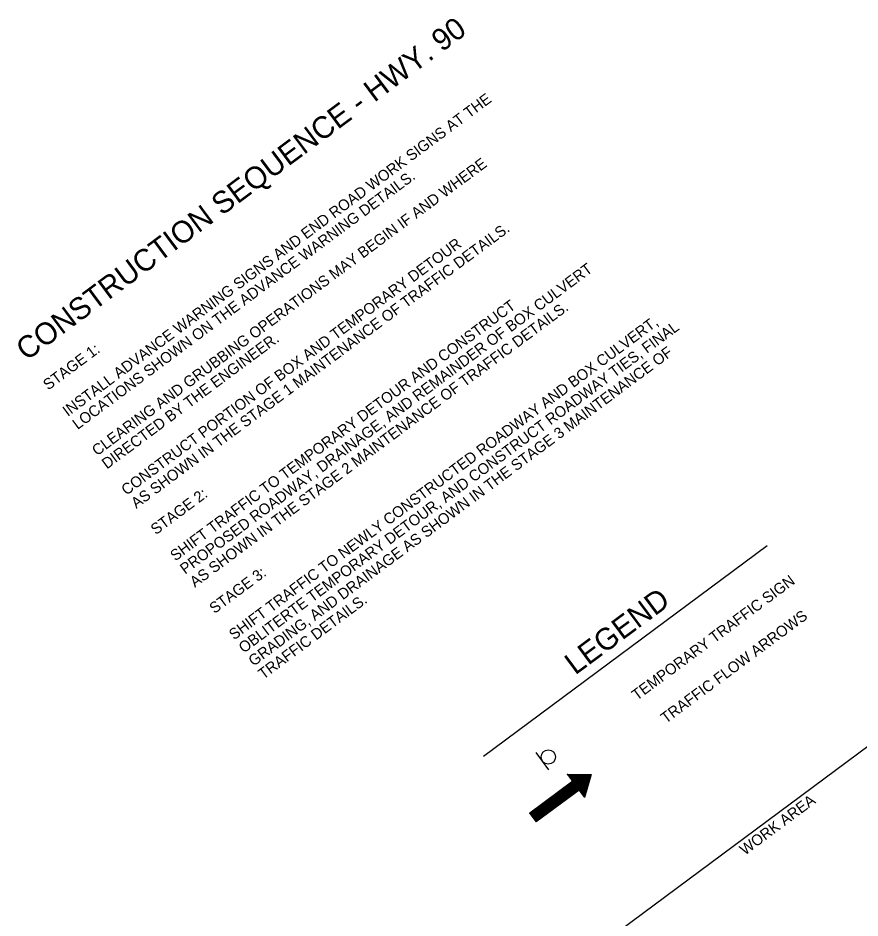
# Model space of a CAD drawing. Extents: x 998982 to 1000630, y 1875366 to 1876934.
# Drawn here: x 999331.9 to 999794.4, y 1876029.3 to 1876523.6 of the extents above; entities that cross this region are included whole.
import ezdxf

# ---------------------------------------------------------------- set-up
doc = ezdxf.new("R2010")
doc.units = 0
for name, color, linetype in [('R_Border Prem', 7, 'Continuous'), ('R_Draft', 7, 'Continuous'), ('STAMP', 7, 'Continuous')]:
    doc.layers.add(name, color=color, linetype=linetype)

msp = doc.modelspace()

# ---------------------------------------------------------------- linework, layer by layer
at = {"layer": 'R_Border Prem'}
for p, q in [((999587.66, 1876118.2), (999743.35, 1876233.81)), ((999633.68, 1876108.29), (999633.69, 1876108.36)), ((999633.76, 1876108.18), (999633.79, 1876108.36)), ((999633.84, 1876108.07), (999633.89, 1876108.36)), ((999633.93, 1876107.95), (999633.99, 1876108.36)), ((999634.01, 1876107.84), (999634.09, 1876108.36)), ((999634.1, 1876107.72), (999634.19, 1876108.35)), ((999634.18, 1876107.61), (999634.29, 1876108.35)), ((999634.27, 1876107.5), (999634.39, 1876108.35)), ((999634.35, 1876107.38), (999634.49, 1876108.35)), ((999634.43, 1876107.27), (999634.59, 1876108.35)), ((999634.52, 1876107.16), (999634.69, 1876108.35)), ((999634.6, 1876107.04), (999634.8, 1876108.34)), ((999634.69, 1876106.93), (999634.9, 1876108.34)), ((999634.77, 1876106.82), (999635, 1876108.34)), ((999634.86, 1876106.7), (999635.1, 1876108.34)), ((999634.94, 1876106.59), (999635.2, 1876108.34)), ((999635.02, 1876106.48), (999635.3, 1876108.34)), ((999635.11, 1876106.36), (999635.4, 1876108.33)), ((999635.19, 1876106.25), (999635.5, 1876108.33)), ((999635.28, 1876106.14), (999635.6, 1876108.33)), ((999635.36, 1876106.02), (999635.7, 1876108.33)), ((999635.4, 1876096.02), (999637.22, 1876108.3)), ((999635.45, 1876105.91), (999635.8, 1876108.33)), ((999635.51, 1876096.1), (999637.32, 1876108.3)), ((999635.53, 1876105.79), (999635.9, 1876108.32)), ((999635.62, 1876105.68), (999636.01, 1876108.32)), ((999635.63, 1876096.19), (999637.42, 1876108.3)), ((999635.7, 1876105.57), (999636.11, 1876108.32)), ((999635.74, 1876096.27), (999637.52, 1876108.3)), ((999635.78, 1876105.45), (999636.21, 1876108.32)), ((999635.85, 1876096.36), (999637.62, 1876108.29)), ((999635.87, 1876105.34), (999636.31, 1876108.32)), ((999635.95, 1876105.23), (999636.41, 1876108.32)), ((999635.97, 1876096.44), (999637.72, 1876108.29)), ((999636.04, 1876105.11), (999636.51, 1876108.31)), ((999636.08, 1876096.53), (999637.82, 1876108.29)), ((999636.12, 1876105), (999636.61, 1876108.31)), ((999636.2, 1876096.61), (999637.92, 1876108.29)), ((999636.21, 1876104.89), (999636.71, 1876108.31)), ((999636.29, 1876104.77), (999636.81, 1876108.31)), ((999636.31, 1876096.69), (999638.02, 1876108.29)), ((999636.37, 1876104.66), (999636.91, 1876108.31)), ((999636.42, 1876096.78), (999638.12, 1876108.28)), ((999636.46, 1876104.55), (999637.01, 1876108.3)), ((999636.54, 1876104.43), (999637.11, 1876108.3)), ((999636.54, 1876096.86), (999638.22, 1876108.28)), ((999636.65, 1876096.95), (999638.32, 1876108.28)), ((999636.76, 1876097.03), (999638.43, 1876108.28)), ((999636.88, 1876097.12), (999638.53, 1876108.28)), ((999636.99, 1876097.2), (999638.63, 1876108.28)), ((999637.1, 1876097.28), (999638.73, 1876108.27)), ((999637.22, 1876097.37), (999638.83, 1876108.27)), ((999637.33, 1876097.45), (999638.93, 1876108.27)), ((999637.44, 1876097.54), (999639.03, 1876108.27)), ((999637.56, 1876097.62), (999639.13, 1876108.27)), ((999637.67, 1876097.71), (999639.23, 1876108.26)), ((999637.79, 1876097.79), (999639.33, 1876108.26)), ((999637.9, 1876097.87), (999639.43, 1876108.26)), ((999638.01, 1876097.96), (999639.53, 1876108.26)), ((999638.13, 1876098.04), (999639.63, 1876108.26)), ((999638.24, 1876098.13), (999639.74, 1876108.26)), ((999638.35, 1876098.21), (999639.84, 1876108.25)), ((999638.47, 1876098.3), (999639.94, 1876108.25)), ((999638.58, 1876098.38), (999640.04, 1876108.25)), ((999638.69, 1876098.46), (999640.14, 1876108.25)), ((999638.81, 1876098.55), (999640.24, 1876108.25)), ((999638.92, 1876098.63), (999640.34, 1876108.25)), ((999639.03, 1876098.72), (999640.44, 1876108.24)), ((999639.15, 1876098.8), (999640.54, 1876108.24)), ((999639.26, 1876098.89), (999640.64, 1876108.24)), ((999639.37, 1876098.97), (999640.74, 1876108.24)), ((999639.49, 1876099.05), (999640.84, 1876108.24)), ((999639.6, 1876099.14), (999640.95, 1876108.23)), ((999639.72, 1876099.22), (999641.05, 1876108.23)), ((999639.83, 1876099.31), (999641.15, 1876108.23)), ((999639.94, 1876099.39), (999641.25, 1876108.23)), ((999640.06, 1876099.48), (999641.35, 1876108.23)), ((999640.17, 1876099.55), (999641.45, 1876108.23)), ((999640.25, 1876099.44), (999641.55, 1876108.22)), ((999640.34, 1876099.32), (999641.65, 1876108.22)), ((999640.42, 1876099.21), (999641.75, 1876108.22)), ((999640.51, 1876099.1), (999641.85, 1876108.22)), ((999640.59, 1876098.98), (999641.95, 1876108.22)), ((999640.67, 1876098.87), (999642.05, 1876108.21)), ((999640.76, 1876098.75), (999642.16, 1876108.21)), ((999640.84, 1876098.64), (999642.26, 1876108.21)), ((999640.93, 1876098.53), (999642.36, 1876108.21)), ((999641.01, 1876098.41), (999642.46, 1876108.21)), ((999641.1, 1876098.3), (999642.56, 1876108.21)), ((999641.18, 1876098.19), (999642.66, 1876108.2)), ((999641.26, 1876098.07), (999642.76, 1876108.2)), ((999641.35, 1876097.96), (999642.86, 1876108.2)), ((999641.43, 1876097.85), (999642.96, 1876108.2)), ((999641.52, 1876097.73), (999643.06, 1876108.2)), ((999641.6, 1876097.62), (999643.16, 1876108.19)), ((999641.69, 1876097.51), (999643.26, 1876108.19)), ((999641.77, 1876097.39), (999643.37, 1876108.19)), ((999641.85, 1876097.28), (999643.47, 1876108.19)), ((999641.94, 1876097.17), (999643.57, 1876108.19)), ((999642.02, 1876097.05), (999643.67, 1876108.19)), ((999642.11, 1876096.94), (999643.77, 1876108.18)), ((999642.19, 1876096.82), (999643.87, 1876108.18)), ((999642.28, 1876096.71), (999643.97, 1876108.18)), ((999642.36, 1876096.6), (999644.07, 1876108.18)), ((999642.44, 1876096.48), (999644.17, 1876108.18)), ((999642.53, 1876096.37), (999644.27, 1876108.17)), ((999642.61, 1876096.26), (999644.37, 1876108.17)), ((999642.7, 1876096.14), (999644.47, 1876108.17)), ((999642.78, 1876096.03), (999644.58, 1876108.17)), ((999642.87, 1876095.92), (999644.68, 1876108.17)), ((999642.95, 1876095.8), (999644.78, 1876108.17)), ((999643.03, 1876095.69), (999644.88, 1876108.16)), ((999643.12, 1876095.58), (999644.98, 1876108.16)), ((999643.3, 1876096.14), (999645.08, 1876108.16)), ((999643.52, 1876096.89), (999645.18, 1876108.16)), ((999643.73, 1876097.64), (999645.28, 1876108.16)), ((999643.94, 1876098.39), (999645.38, 1876108.16)), ((999644.15, 1876099.14), (999645.48, 1876108.15)), ((999644.36, 1876099.89), (999645.58, 1876108.15)), ((999644.57, 1876100.64), (999645.68, 1876108.15)), ((999644.79, 1876101.39), (999645.78, 1876108.15)), ((999645, 1876102.14), (999645.89, 1876108.15)), ((999645.21, 1876102.88), (999645.99, 1876108.14)), ((999645.42, 1876103.63), (999646.09, 1876108.14)), ((999645.63, 1876104.38), (999646.19, 1876108.14)), ((999645.84, 1876105.13), (999646.29, 1876108.14)), ((999646.06, 1876105.88), (999646.39, 1876108.14)), ((999646.27, 1876106.63), (999646.49, 1876108.14)), ((999646.48, 1876107.38), (999646.59, 1876108.13)), ((999646.69, 1876108.13), (999646.69, 1876108.13)), ((999633.02, 1876094.25), (999634.25, 1876102.62)), ((999633.13, 1876094.33), (999634.37, 1876102.71)), ((999633.24, 1876094.42), (999634.48, 1876102.79)), ((999633.36, 1876094.5), (999634.59, 1876102.87)), ((999633.47, 1876094.59), (999634.71, 1876102.96)), ((999633.58, 1876094.67), (999634.82, 1876103.04)), ((999633.7, 1876094.76), (999634.93, 1876103.13)), ((999633.81, 1876094.84), (999635.05, 1876103.21)), ((999633.92, 1876094.92), (999635.16, 1876103.3)), ((999634.04, 1876095.01), (999635.28, 1876103.38)), ((999634.15, 1876095.09), (999635.39, 1876103.46)), ((999634.27, 1876095.18), (999635.5, 1876103.55)), ((999634.38, 1876095.26), (999635.62, 1876103.63)), ((999634.49, 1876095.35), (999635.73, 1876103.72)), ((999634.61, 1876095.43), (999635.84, 1876103.8)), ((999634.72, 1876095.51), (999635.96, 1876103.89)), ((999634.83, 1876095.6), (999636.07, 1876103.97)), ((999634.95, 1876095.68), (999636.18, 1876104.06)), ((999635.06, 1876095.77), (999636.3, 1876104.14)), ((999635.17, 1876095.85), (999636.41, 1876104.22)), ((999635.29, 1876095.94), (999636.52, 1876104.31)), ((999626.43, 1876089.36), (999627.67, 1876097.73)), ((999626.54, 1876089.44), (999627.78, 1876097.82)), ((999626.66, 1876089.53), (999627.9, 1876097.9)), ((999626.77, 1876089.61), (999628.01, 1876097.98)), ((999626.89, 1876089.7), (999628.12, 1876098.07)), ((999627, 1876089.78), (999628.24, 1876098.15)), ((999627.11, 1876089.87), (999628.35, 1876098.24)), ((999627.23, 1876089.95), (999628.46, 1876098.32)), ((999627.34, 1876090.03), (999628.58, 1876098.41)), ((999627.45, 1876090.12), (999628.69, 1876098.49)), ((999627.57, 1876090.2), (999628.8, 1876098.58)), ((999627.68, 1876090.29), (999628.92, 1876098.66)), ((999627.79, 1876090.37), (999629.03, 1876098.74)), ((999627.91, 1876090.46), (999629.14, 1876098.83)), ((999628.02, 1876090.54), (999629.26, 1876098.91)), ((999628.13, 1876090.62), (999629.37, 1876099)), ((999628.25, 1876090.71), (999629.48, 1876099.08)), ((999628.36, 1876090.79), (999629.6, 1876099.17)), ((999628.47, 1876090.88), (999629.71, 1876099.25)), ((999628.59, 1876090.96), (999629.83, 1876099.33)), ((999628.7, 1876091.05), (999629.94, 1876099.42)), ((999628.82, 1876091.13), (999630.05, 1876099.5)), ((999628.93, 1876091.21), (999630.17, 1876099.59)), ((999629.04, 1876091.3), (999630.28, 1876099.67)), ((999629.16, 1876091.38), (999630.39, 1876099.76)), ((999629.27, 1876091.47), (999630.51, 1876099.84)), ((999629.38, 1876091.55), (999630.62, 1876099.92)), ((999629.5, 1876091.64), (999630.73, 1876100.01)), ((999629.61, 1876091.72), (999630.85, 1876100.09)), ((999629.72, 1876091.8), (999630.96, 1876100.18)), ((999629.84, 1876091.89), (999631.07, 1876100.26)), ((999629.95, 1876091.97), (999631.19, 1876100.35)), ((999630.06, 1876092.06), (999631.3, 1876100.43)), ((999630.18, 1876092.14), (999631.41, 1876100.51)), ((999630.29, 1876092.23), (999631.53, 1876100.6)), ((999630.4, 1876092.31), (999631.64, 1876100.68)), ((999630.52, 1876092.39), (999631.76, 1876100.77)), ((999630.63, 1876092.48), (999631.87, 1876100.85)), ((999630.75, 1876092.56), (999631.98, 1876100.94)), ((999630.86, 1876092.65), (999632.1, 1876101.02)), ((999630.97, 1876092.73), (999632.21, 1876101.1)), ((999631.09, 1876092.82), (999632.32, 1876101.19)), ((999631.2, 1876092.9), (999632.44, 1876101.27)), ((999631.31, 1876092.98), (999632.55, 1876101.36)), ((999631.43, 1876093.07), (999632.66, 1876101.44)), ((999631.54, 1876093.15), (999632.78, 1876101.53)), ((999631.65, 1876093.24), (999632.89, 1876101.61)), ((999631.77, 1876093.32), (999633, 1876101.69)), ((999631.88, 1876093.41), (999633.12, 1876101.78)), ((999631.99, 1876093.49), (999633.23, 1876101.86)), ((999632.11, 1876093.57), (999633.35, 1876101.95)), ((999632.22, 1876093.66), (999633.46, 1876102.03)), ((999632.34, 1876093.74), (999633.57, 1876102.12)), ((999632.45, 1876093.83), (999633.69, 1876102.2)), ((999632.56, 1876093.91), (999633.8, 1876102.28)), ((999632.68, 1876094), (999633.91, 1876102.37)), ((999632.79, 1876094.08), (999634.03, 1876102.45)), ((999632.9, 1876094.16), (999634.14, 1876102.54)), ((999619.73, 1876084.38), (999620.97, 1876092.76)), ((999619.85, 1876084.47), (999621.08, 1876092.84)), ((999619.96, 1876084.55), (999621.2, 1876092.93)), ((999620.07, 1876084.64), (999621.31, 1876093.01)), ((999620.19, 1876084.72), (999621.42, 1876093.09)), ((999620.3, 1876084.81), (999621.54, 1876093.18)), ((999620.41, 1876084.89), (999621.65, 1876093.26)), ((999620.53, 1876084.98), (999621.76, 1876093.35)), ((999620.64, 1876085.06), (999621.88, 1876093.43)), ((999620.75, 1876085.14), (999621.99, 1876093.52)), ((999620.87, 1876085.23), (999622.1, 1876093.6)), ((999620.98, 1876085.31), (999622.22, 1876093.69)), ((999621.09, 1876085.4), (999622.33, 1876093.77)), ((999621.21, 1876085.48), (999622.44, 1876093.85)), ((999621.32, 1876085.57), (999622.56, 1876093.94)), ((999621.44, 1876085.65), (999622.67, 1876094.02)), ((999621.55, 1876085.73), (999622.79, 1876094.11)), ((999621.66, 1876085.82), (999622.9, 1876094.19)), ((999621.78, 1876085.9), (999623.01, 1876094.28)), ((999621.89, 1876085.99), (999623.13, 1876094.36)), ((999622, 1876086.07), (999623.24, 1876094.44)), ((999622.12, 1876086.16), (999623.35, 1876094.53)), ((999622.23, 1876086.24), (999623.47, 1876094.61)), ((999622.34, 1876086.32), (999623.58, 1876094.7)), ((999622.46, 1876086.41), (999623.69, 1876094.78)), ((999622.57, 1876086.49), (999623.81, 1876094.87)), ((999622.68, 1876086.58), (999623.92, 1876094.95)), ((999622.8, 1876086.66), (999624.03, 1876095.03)), ((999622.91, 1876086.75), (999624.15, 1876095.12)), ((999623.02, 1876086.83), (999624.26, 1876095.2)), ((999623.14, 1876086.91), (999624.38, 1876095.29)), ((999623.25, 1876087), (999624.49, 1876095.37)), ((999623.37, 1876087.08), (999624.6, 1876095.46)), ((999623.48, 1876087.17), (999624.72, 1876095.54)), ((999623.59, 1876087.25), (999624.83, 1876095.62)), ((999623.71, 1876087.34), (999624.94, 1876095.71)), ((999623.82, 1876087.42), (999625.06, 1876095.79)), ((999623.93, 1876087.5), (999625.17, 1876095.88)), ((999624.05, 1876087.59), (999625.28, 1876095.96)), ((999624.16, 1876087.67), (999625.4, 1876096.05)), ((999624.27, 1876087.76), (999625.51, 1876096.13)), ((999624.39, 1876087.84), (999625.62, 1876096.21)), ((999624.5, 1876087.93), (999625.74, 1876096.3)), ((999624.61, 1876088.01), (999625.85, 1876096.38)), ((999624.73, 1876088.09), (999625.96, 1876096.47)), ((999624.84, 1876088.18), (999626.08, 1876096.55)), ((999624.95, 1876088.26), (999626.19, 1876096.64)), ((999625.07, 1876088.35), (999626.31, 1876096.72)), ((999625.18, 1876088.43), (999626.42, 1876096.8)), ((999625.3, 1876088.52), (999626.53, 1876096.89)), ((999625.41, 1876088.6), (999626.65, 1876096.97)), ((999625.52, 1876088.68), (999626.76, 1876097.06)), ((999625.64, 1876088.77), (999626.87, 1876097.14)), ((999625.75, 1876088.85), (999626.99, 1876097.23)), ((999625.86, 1876088.94), (999627.1, 1876097.31)), ((999625.98, 1876089.02), (999627.21, 1876097.39)), ((999626.09, 1876089.11), (999627.33, 1876097.48)), ((999626.2, 1876089.19), (999627.44, 1876097.56)), ((999626.32, 1876089.27), (999627.55, 1876097.65)), ((999613.95, 1876085.63), (999614.27, 1876087.78)), ((999614.04, 1876085.52), (999614.38, 1876087.87)), ((999614.12, 1876085.4), (999614.5, 1876087.95)), ((999614.2, 1876085.29), (999614.61, 1876088.04)), ((999614.29, 1876085.17), (999614.72, 1876088.12)), ((999614.37, 1876085.06), (999614.84, 1876088.2)), ((999614.46, 1876084.95), (999614.95, 1876088.29)), ((999614.54, 1876084.83), (999615.06, 1876088.37)), ((999614.63, 1876084.72), (999615.18, 1876088.46)), ((999614.71, 1876084.61), (999615.29, 1876088.54)), ((999614.79, 1876084.49), (999615.41, 1876088.63)), ((999614.88, 1876084.38), (999615.52, 1876088.71)), ((999614.96, 1876084.27), (999615.63, 1876088.8)), ((999615.05, 1876084.15), (999615.75, 1876088.88)), ((999615.13, 1876084.04), (999615.86, 1876088.96)), ((999615.22, 1876083.93), (999615.97, 1876089.05)), ((999615.3, 1876083.81), (999616.09, 1876089.13)), ((999615.38, 1876083.7), (999616.2, 1876089.22)), ((999615.47, 1876083.58), (999616.31, 1876089.3)), ((999615.55, 1876083.47), (999616.43, 1876089.39)), ((999615.64, 1876083.36), (999616.54, 1876089.47)), ((999615.72, 1876083.24), (999616.65, 1876089.55)), ((999615.81, 1876083.13), (999616.77, 1876089.64)), ((999615.89, 1876083.02), (999616.88, 1876089.72)), ((999615.97, 1876082.9), (999616.99, 1876089.81)), ((999616.06, 1876082.79), (999617.11, 1876089.89)), ((999616.14, 1876082.68), (999617.22, 1876089.98)), ((999616.23, 1876082.56), (999617.34, 1876090.06)), ((999616.31, 1876082.45), (999617.45, 1876090.14)), ((999616.4, 1876082.34), (999617.56, 1876090.23)), ((999616.48, 1876082.22), (999617.68, 1876090.31)), ((999616.57, 1876082.11), (999617.79, 1876090.4)), ((999616.67, 1876082.11), (999617.9, 1876090.48)), ((999616.78, 1876082.19), (999618.02, 1876090.57)), ((999616.89, 1876082.28), (999618.13, 1876090.65)), ((999617.01, 1876082.36), (999618.24, 1876090.73)), ((999617.12, 1876082.45), (999618.36, 1876090.82)), ((999617.23, 1876082.53), (999618.47, 1876090.9)), ((999617.35, 1876082.61), (999618.58, 1876090.99)), ((999617.46, 1876082.7), (999618.7, 1876091.07)), ((999617.57, 1876082.78), (999618.81, 1876091.16)), ((999617.69, 1876082.87), (999618.93, 1876091.24)), ((999617.8, 1876082.95), (999619.04, 1876091.32)), ((999617.92, 1876083.04), (999619.15, 1876091.41)), ((999618.03, 1876083.12), (999619.27, 1876091.49)), ((999618.14, 1876083.2), (999619.38, 1876091.58)), ((999618.26, 1876083.29), (999619.49, 1876091.66)), ((999618.37, 1876083.37), (999619.61, 1876091.75)), ((999618.48, 1876083.46), (999619.72, 1876091.83)), ((999618.6, 1876083.54), (999619.83, 1876091.91)), ((999618.71, 1876083.63), (999619.95, 1876092)), ((999618.82, 1876083.71), (999620.06, 1876092.08)), ((999618.94, 1876083.79), (999620.17, 1876092.17)), ((999619.05, 1876083.88), (999620.29, 1876092.25)), ((999619.16, 1876083.96), (999620.4, 1876092.34)), ((999619.28, 1876084.05), (999620.51, 1876092.42)), ((999619.39, 1876084.13), (999620.63, 1876092.5)), ((999619.5, 1876084.22), (999620.74, 1876092.59)), ((999619.62, 1876084.3), (999620.86, 1876092.67)), ((999613.11, 1876086.76), (999613.13, 1876086.94)), ((999613.19, 1876086.65), (999613.25, 1876087.02)), ((999613.28, 1876086.54), (999613.36, 1876087.11)), ((999613.36, 1876086.42), (999613.48, 1876087.19)), ((999613.45, 1876086.31), (999613.59, 1876087.28)), ((999613.53, 1876086.2), (999613.7, 1876087.36)), ((999613.61, 1876086.08), (999613.82, 1876087.45)), ((999613.7, 1876085.97), (999613.93, 1876087.53)), ((999613.78, 1876085.86), (999614.04, 1876087.61)), ((999613.87, 1876085.74), (999614.16, 1876087.7))]:
    msp.add_line(p, q, dxfattribs=at)
at = {"layer": 'R_Draft'}
for p, q in [((999869.63, 1876176.23), (999622.25, 1875992.54)), ((999633.62, 1876108.36), (999636.6, 1876104.36)), ((999633.62, 1876108.36), (999646.69, 1876108.13)), ((999633.62, 1876108.36), (999636.6, 1876104.36)), ((999633.62, 1876108.36), (999646.69, 1876108.13)), ((999646.69, 1876108.13), (999643.14, 1876095.55)), ((999646.69, 1876108.13), (999643.14, 1876095.55)), ((999636.6, 1876104.36), (999613.03, 1876086.86)), ((999636.6, 1876104.36), (999613.03, 1876086.87)), ((999640.16, 1876099.56), (999616.6, 1876082.06)), ((999640.16, 1876099.56), (999616.6, 1876082.06)), ((999640.16, 1876099.56), (999643.14, 1876095.55)), ((999640.16, 1876099.56), (999643.14, 1876095.55)), ((999613.03, 1876086.87), (999616.6, 1876082.06)), ((999613.03, 1876086.86), (999616.6, 1876082.06))]:
    msp.add_line(p, q, dxfattribs=at)
at = {"layer": 'STAMP'}
msp.add_line((999623.55, 1876110.65), (999616.55, 1876120.09), dxfattribs=at)
msp.add_circle((999623.2, 1876117.71), 3.92, dxfattribs=at)

# ---------------------------------------------------------------- texts
at = {"layer": 'R_Border Prem'}
for s, height, rotation, p in [('CONSTRUCTION SEQUENCE - HWY. 90', 12, 36.6341, (999336.61, 1876334.99)), ('INSTALL ADVANCE WARNING SIGNS AND END ROAD WORK SIGNS AT THE ', 6, 36.6341, (999359.28, 1876304.5)), ('CLEARING AND GRUBBING OPERATIONS MAY BEGIN IF AND WHERE ', 6, 36.6341, (999375.4, 1876282.83)), ('LOCATIONS SHOWN ON THE ADVANCE WARNING DETAILS. ', 6, 36.6341, (999364.66, 1876297.28)), ('AS SHOWN IN THE STAGE 1 MAINTENANCE OF TRAFFIC DETAILS.', 6, 36.6341, (999396.88, 1876253.94)), ('CONSTRUCT PORTION OF BOX AND TEMPORARY DETOUR', 6, 36.6341, (999391.51, 1876261.17)), ('PROPOSED ROADWAY, DRAINAGE, AND REMAINDER OF BOX CULVERT', 6, 36.6341, (999423.73, 1876217.83)), ('SHIFT TRAFFIC TO TEMPORARY DETOUR AND CONSTRUCT ', 6, 36.6341, (999418.36, 1876225.05)), ('AS SHOWN IN THE STAGE 2 MAINTENANCE OF TRAFFIC DETAILS.', 6, 36.6341, (999429.1, 1876210.61)), ('SHIFT TRAFFIC TO NEWLY CONSTRUCTED ROADWAY AND BOX CULVERT, ', 6, 36.6341, (999450.58, 1876181.72)), ('OBLITERTE TEMPORARY DETOUR, AND CONSTRUCT ROADWAY TIES, FINAL', 6, 36.6341, (999455.95, 1876174.5)), ('DIRECTED BY THE ENGINEER.', 6, 36.6341, (999380.77, 1876275.61)), ('STAGE 1: ', 6, 36.6341, (999348.54, 1876318.94)), ('GRADING, AND DRAINAGE AS SHOWN IN THE STAGE 3 MAINTENANCE OF ', 6, 36.6341, (999461.32, 1876167.28)), ('STAGE 2:', 6, 36.6341, (999407.62, 1876239.5)), ('STAGE 3:', 6, 36.6341, (999439.84, 1876196.17)), ('TEMPORARY TRAFFIC SIGN', 6, 36.5953, (999671.87, 1876148.5)), ('LEGEND', 12, 36.5953, (999637.98, 1876162.43)), ('TRAFFIC DETAILS.', 6, 36.6341, (999466.69, 1876160.06)), ('TRAFFIC FLOW ARROWS', 6, 36.5953, (999687.78, 1876135.85)), ('WORK AREA', 6, 36.5953, (999731.15, 1876063.47))]:
    msp.add_text(s, height=height, rotation=rotation, dxfattribs=at).set_placement(p)

doc.saveas('drawing.dxf')
